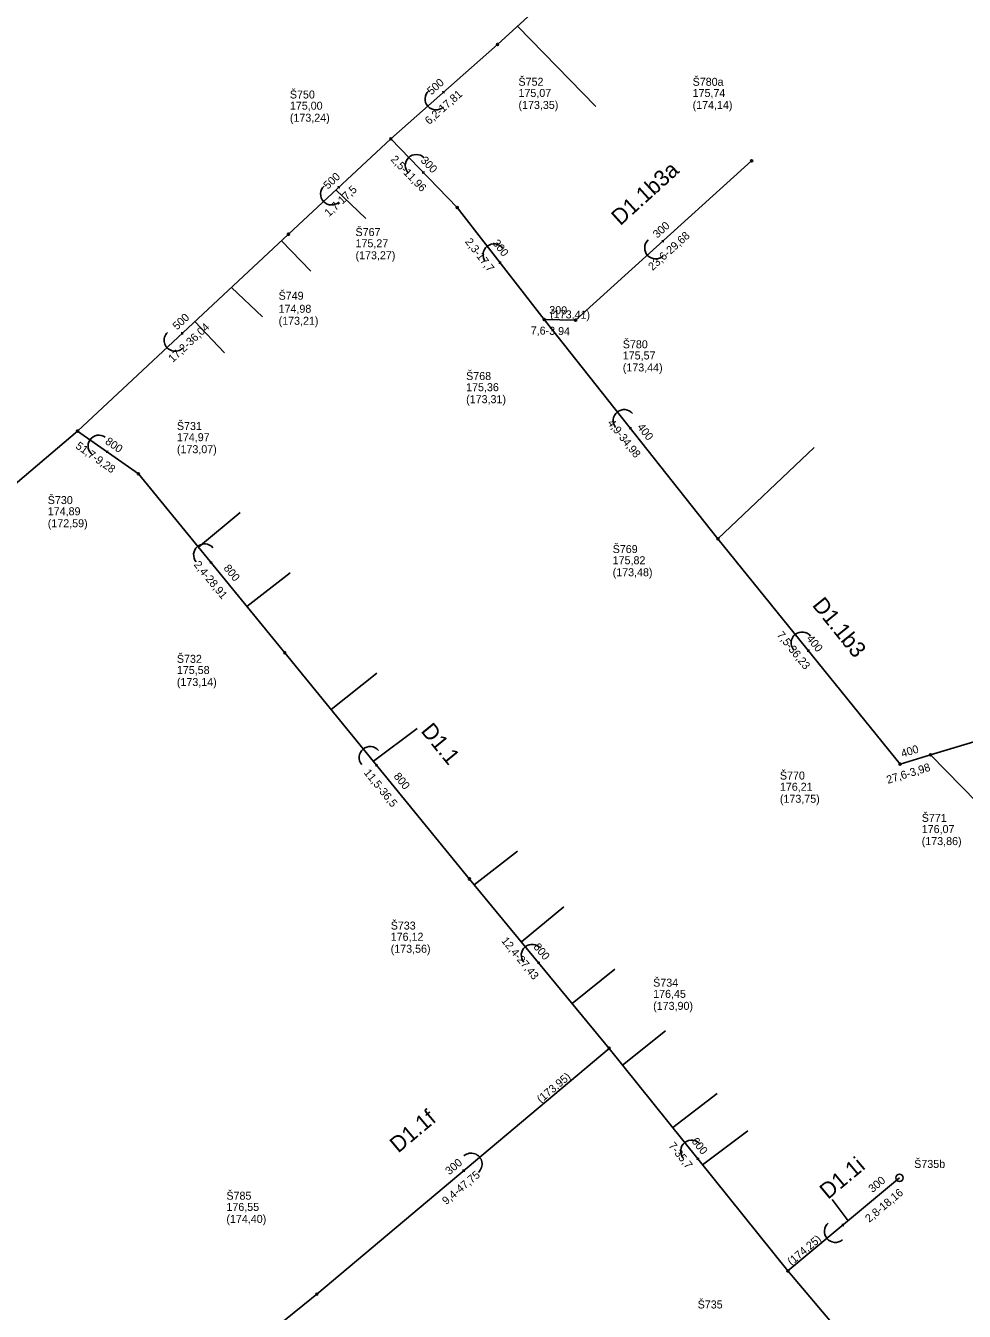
# Model space of a CAD drawing. Extents: x -548529 to -543591, y -1201432 to -1192608.
# Drawn here: x -544931.3 to -544814, y -1193635.3 to -1193474.6 of the extents above; entities that cross this region are included whole.
import ezdxf

# ---------------------------------------------------------------- set-up
doc = ezdxf.new("R2010")
doc.units = 0
for name, color, linetype in [('C3D_Bod-Značky', 7, 'Continuous'), ('C3D_Koridor', 7, 'Continuous'), ('C3D_Křižovatka', 7, 'Continuous'), ('C3D_Netisknutelná', 7, 'Continuous'), ('C3D_PP-zobrazeni v PR', 7, 'Continuous'), ('C3D_PR-Popisek', 7, 'Continuous'), ('C3D_SPR-Popisek', 7, 'Continuous'), ('C3D_Tlakove_potrubi_Popis', 7, 'Continuous'), ('C3D_ZPR-Formaty', 7, 'Continuous')]:
    doc.layers.add(name, color=color, linetype=linetype)

# ---------------------------------------------------------------- blocks, each defined once
blk = doc.blocks.new('100')
at = {"layer": 'Defpoints'}
blk.add_circle((0, 0), 0.127, dxfattribs=at)
blk = doc.blocks.new('101')
at = {"layer": 'Defpoints'}
blk.add_circle((0, 0), 0.463, dxfattribs=at)
blk = doc.blocks.new('91')
at = {"layer": 'Defpoints'}
blk.add_lwpolyline([(0.08, 0.14), (0.19, 0), (0.08, -0.14)], dxfattribs=at)
blk.add_arc((1.37, 0), 1.37, 270, 90, dxfattribs=at)
blk = doc.blocks.new('86')
at = {"layer": 'Defpoints'}
blk.add_lwpolyline([(0.08, 0.14), (0.19, 0), (0.08, -0.14)], dxfattribs=at)
blk.add_arc((1.37, 0), 1.37, 270, 90, dxfattribs=at)

msp = doc.modelspace()

# ---------------------------------------------------------------- linework, layer by layer
at = {"layer": 'C3D_Bod-Značky'}
for points in [[(-544851.303, -1193457.748), (-544872.308, -1193476.946)], [(-544872.308, -1193476.946), (-544885.651, -1193488.75)], [(-544885.651, -1193488.75), (-544898.453, -1193500.683)], [(-544877.337, -1193497.346), (-544885.651, -1193488.75)], [(-544840.54, -1193491.5), (-544862.54, -1193511.42)], [(-544866.481, -1193511.325), (-544877.337, -1193497.346)], [(-544898.453, -1193500.683), (-544924.795, -1193525.275)], [(-544844.754, -1193538.736), (-544866.481, -1193511.325)], [(-544862.54, -1193511.42), (-544866.481, -1193511.325)], [(-544924.795, -1193525.275), (-544947.898, -1193544.875)], [(-544917.202, -1193530.615), (-544924.795, -1193525.275)], [(-544898.887, -1193552.989), (-544917.202, -1193530.615)], [(-544821.99, -1193566.92), (-544844.754, -1193538.736)], [(-544875.81, -1193581.27), (-544898.887, -1193552.989)], [(-544802.07, -1193560.9), (-544818.19, -1193565.74)], [(-544818.19, -1193565.74), (-544821.99, -1193566.92)], [(-544858.362, -1193602.437), (-544875.81, -1193581.27)], [(-544894.906, -1193633.168), (-544858.362, -1193602.437)], [(-544836, -1193630.262), (-544858.362, -1193602.437)], [(-544822.063, -1193618.624), (-544836, -1193630.262)], [(-544821.397, -1193647.55), (-544836, -1193630.262)], [(-544920.416, -1193653.842), (-544894.906, -1193633.168)]]:
    msp.add_lwpolyline(points, dxfattribs=at)
at = {"layer": 'C3D_Koridor'}
for points in [[(-544869.808, -1193474.661), (-544860.021, -1193484.722)], [(-544892.504, -1193495.141), (-544888.751, -1193498.717)], [(-544899.33, -1193501.502), (-544895.655, -1193505.284)], [(-544905.565, -1193507.323), (-544901.693, -1193510.985)], [(-544910.127, -1193511.581), (-544906.416, -1193515.501)], [(-544844.754, -1193538.736), (-544832.714, -1193527.337)], [(-544909.703, -1193539.776), (-544904.495, -1193535.469)], [(-544903.631, -1193547.193), (-544898.246, -1193542.989)], [(-544893.108, -1193560.071), (-544887.4, -1193555.53)], [(-544887.83, -1193566.539), (-544882.339, -1193562.478)], [(-544818.19, -1193565.74), (-544794.95, -1193589.492)], [(-544875.219, -1193581.987), (-544869.818, -1193577.785)], [(-544869.324, -1193589.139), (-544864.037, -1193584.764)], [(-544862.978, -1193596.837), (-544857.632, -1193592.55)], [(-544856.677, -1193604.534), (-544851.308, -1193600.24)], [(-544850.407, -1193612.336), (-544844.848, -1193608.09)], [(-544846.669, -1193616.987), (-544841.008, -1193612.737)], [(-544828.495, -1193623.995), (-544830.467, -1193621.345)]]:
    msp.add_lwpolyline(points, dxfattribs=at)

# ---------------------------------------------------------------- block references
at = {"layer": 'C3D_PP-zobrazeni v PR'}
for name, p, xscale, yscale, rotation in [('100', (-544872.308, -1193476.946), 1.0000000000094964, 1.0000000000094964, -137.9999986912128), ('100', (-544885.651, -1193488.75), 1.00000000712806, 1.00000000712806, -136.99999943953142), ('100', (-544840.54, -1193491.5), 1.00000000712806, 1.00000000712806, 43.0000005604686), ('100', (-544877.337, -1193497.346), 1.0000000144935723, 1.0000000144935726, 130.99999910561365), ('100', (-544898.453, -1193500.683), 1.0000000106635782, 1.0000000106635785, -135.99999834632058), ('100', (-544866.481, -1193511.325), 1.000000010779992, 1.0000000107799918, 128.99999891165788), ('100', (-544862.54, -1193511.42), 1.0275072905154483, 1.027507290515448, -155.31089431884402), ('100', (-544924.795, -1193525.275), 1.0002788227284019, 1.0002788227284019, -176.70930040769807), ('100', (-544917.202, -1193530.615), 1.0000000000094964, 1.0000000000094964, 137.9999986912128), ('100', (-544844.754, -1193538.736), 1.000000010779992, 1.0000000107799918, 128.99999891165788), ('100', (-544898.887, -1193552.989), 1.0000000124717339, 1.0000000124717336, 130.0000013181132), ('100', (-544821.99, -1193566.92), 1.0365458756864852, 1.0365458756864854, 158.02850914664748), ('100', (-544818.19, -1193565.74), 1.035124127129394, 1.0351241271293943, -157.49634583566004), ('100', (-544875.81, -1193581.27), 1.0000000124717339, 1.0000000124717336, 130.0000013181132), ('100', (-544858.362, -1193602.437), 1.0000000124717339, 1.0000000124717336, 130.0000013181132), ('101', (-544822.063, -1193618.624), 1.0000000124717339, 1.0000000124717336, 40.00000131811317), ('100', (-544836, -1193630.262), 1.0000000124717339, 1.0000000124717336, 130.0000013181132), ('100', (-544894.906, -1193633.168), 1.0000000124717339, 1.0000000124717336, -139.99999868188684)]:
    msp.add_blockref(name, p, dxfattribs=dict(at, xscale=xscale, yscale=yscale, rotation=rotation))
at = {"layer": 'C3D_SPR-Popisek'}
for name, p, xscale, yscale, rotation in [('91', (-544878.979, -1193482.848), 1.0000000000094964, 1.0000000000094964, -137.9999986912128), ('91', (-544881.494, -1193493.048), 0.999999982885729, 0.9999999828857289, 135), ('91', (-544892.052, -1193494.716), 1.00000000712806, 1.00000000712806, -136.99999943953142), ('91', (-544851.54, -1193501.46), 1.00000000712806, 1.00000000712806, -136.99999943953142), ('91', (-544871.909, -1193504.336), 1.000000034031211, 1.0000000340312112, 128.00000040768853), ('91', (-544911.624, -1193512.979), 1.0000000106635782, 1.0000000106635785, -135.99999834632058), ('86', (-544855.617, -1193525.03), 1.000000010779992, 1.0000000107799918, 128.99999891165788), ('91', (-544920.998, -1193527.945), 1.000000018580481, 1.000000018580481, 144.99999976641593), ('91', (-544908.045, -1193541.802), 1.0000000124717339, 1.0000000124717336, 130.0000013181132), ('86', (-544833.372, -1193552.828), 1.000000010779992, 1.0000000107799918, 128.99999891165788), ('91', (-544887.349, -1193567.13), 1.0000000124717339, 1.0000000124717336, 130.0000013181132), ('91', (-544867.086, -1193591.854), 1.0000000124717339, 1.0000000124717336, 130.0000013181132), ('91', (-544847.181, -1193616.35), 1.000000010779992, 1.0000000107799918, 128.99999891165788), ('91', (-544876.634, -1193617.802), 1.0000000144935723, 1.0000000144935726, 40.99999910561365), ('91', (-544829.032, -1193624.443), 1.0000000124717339, 1.0000000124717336, -139.99999868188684)]:
    msp.add_blockref(name, p, dxfattribs=dict(at, xscale=xscale, yscale=yscale, rotation=rotation))

# ---------------------------------------------------------------- texts
at = {"layer": 'C3D_Křižovatka'}
for s, p in [('Š752', (-544869.688, -1193482.116)), ('Š780a', (-544847.92, -1193482.12)), ('Š750', (-544898.261, -1193483.71)), ('Š767', (-544890.057, -1193500.906)), ('Š749', (-544899.673, -1193508.863)), ('Š780', (-544856.65, -1193514.93)), ('Š768', (-544876.231, -1193518.895)), ('Š731', (-544912.382, -1193525.145)), ('Š730', (-544928.525, -1193534.405)), ('Š769', (-544857.914, -1193540.526)), ('Š732', (-544912.387, -1193554.249)), ('Š770', (-544837.01, -1193568.84)), ('Š771', (-544819.28, -1193574.13)), ('Š733', (-544885.66, -1193587.59)), ('Š734', (-544852.852, -1193594.727)), ('Š735b', (-544820.223, -1193617.384)), ('Š785', (-544906.196, -1193621.358)), ('Š735', (-544847.29, -1193634.952))]:
    msp.add_text(s, height=1, dxfattribs=at).set_placement(p)
at = {"layer": 'C3D_Netisknutelná'}
for s, rotation, p in [('D1.1b3a', 42.16, (-544856.962, -1193499.677)), ('D1.1b3', 308.93, (-544833.053, -1193547.071)), ('D1.1', 309.21, (-544881.976, -1193562.795)), ('D1.1f', 40.06, (-544884.72, -1193615.594)), ('D1.1i', 39.86, (-544830.998, -1193621.392))]:
    msp.add_text(s, height=2, rotation=rotation, dxfattribs=at).set_placement(p)
at = {"layer": 'C3D_PR-Popisek'}
for s, rotation, p in [('500', 41.5, (-544880.575, -1193483.331)), ('300', 314.04, (-544881.994, -1193491.522)), ('500', 42.99, (-544893.51, -1193495.115)), ('300', 42.16, (-544852.34, -1193501.236)), ('300', 307.83, (-544872.994, -1193501.8)), ('300', 358.62, (-544865.853, -1193510.64)), ('500', 43.03, (-544912.367, -1193512.712)), ('400', 308.4, (-544854.905, -1193524.806)), ('800', 324.88, (-544921.436, -1193526.779)), ('800', 309.3, (-544906.609, -1193542.444)), ('400', 308.93, (-544833.74, -1193551.261)), ('400', 17.25, (-544821.706, -1193566.095)), ('800', 309.21, (-544885.354, -1193568.459)), ('800', 309.5, (-544867.876, -1193589.787)), ('600', 308.79, (-544848.118, -1193614.069)), ('300', 40.06, (-544878.327, -1193618.316)), ('300', 39.86, (-544825.436, -1193620.533))]:
    msp.add_text(s, height=1, rotation=rotation, dxfattribs=at).set_placement(p)
at = {"layer": 'C3D_Tlakove_potrubi_Popis'}
for s, p in [('175,07 ', (-544869.688, -1193483.516)), ('175,74 ', (-544847.92, -1193483.52)), ('175,00 ', (-544898.261, -1193485.11)), ('(173,35)', (-544869.688, -1193485.016)), ('(174,14)', (-544847.92, -1193485.02)), ('(173,24)', (-544898.261, -1193486.61)), ('175,27 ', (-544890.057, -1193502.306)), ('(173,27)', (-544890.057, -1193503.806)), ('174,98 ', (-544899.673, -1193510.493)), ('(173,21)', (-544899.673, -1193511.993)), ('175,57 ', (-544856.65, -1193516.33)), ('(173,44)', (-544856.65, -1193517.83)), ('175,36 ', (-544876.231, -1193520.295)), ('(173,31)', (-544876.231, -1193521.795)), ('174,97 ', (-544912.382, -1193526.545)), ('(173,07)', (-544912.382, -1193528.045)), ('(172,59)', (-544928.525, -1193537.305)), ('174,89 ', (-544928.525, -1193535.805)), ('175,82 ', (-544857.914, -1193541.926)), ('(173,48)', (-544857.914, -1193543.426)), ('175,58 ', (-544912.387, -1193555.649)), ('(173,14)', (-544912.387, -1193557.149)), ('176,21 ', (-544837.01, -1193570.24)), ('(173,75)', (-544837.01, -1193571.74)), ('176,07 ', (-544819.28, -1193575.53)), ('(173,86)', (-544819.28, -1193577.03)), ('176,12 ', (-544885.66, -1193588.99)), ('(173,56)', (-544885.66, -1193590.49)), ('176,45 ', (-544852.852, -1193596.127)), ('(173,90)', (-544852.852, -1193597.627)), ('176,55 ', (-544906.196, -1193622.758)), ('(174,40)', (-544906.196, -1193624.258))]:
    msp.add_text(s, height=1, dxfattribs=at).set_placement(p)
at = {"layer": 'C3D_ZPR-Formaty'}
for s, rotation, p in [('6,2-17,81', 41.5, (-544880.849, -1193487.038)), ('2,5-11,96', 314.04, (-544885.737, -1193491.394)), ('1,7-17,5', 42.99, (-544893.381, -1193498.554)), ('23,6-29,68', 42.16, (-544852.925, -1193505.278)), ('2,3-17,7', 307.83, (-544876.42, -1193501.622)), ('  (173,41)   ', 358.62, (-544866.476, -1193511.125)), ('17,2-36,04', 43.03, (-544912.895, -1193516.765)), ('7,6-3,94', 358.62, (-544868.166, -1193513.185)), ('4,9-34,98', 308.4, (-544858.619, -1193524.299)), ('51,7-9,28', 324.88, (-544925.14, -1193527.351)), ('2,4-28,91', 309.3, (-544910.333, -1193542.001)), ('7,5-36,23', 308.93, (-544837.455, -1193550.79)), ('11,5-36,5', 309.21, (-544889.076, -1193568.012)), ('27,6-3,98', 17.25, (-544823.509, -1193569.383)), ('12,4-27,43', 309.5, (-544871.89, -1193589.017)), ('  (173,95)   ', 40.06, (-544867.446, -1193609.814)), ('7-35,7', 308.79, (-544850.995, -1193614.644)), ('9,4-47,75', 40.06, (-544878.722, -1193622.045)), ('2,8-18,16', 39.86, (-544825.842, -1193624.258)), ('  (174,25)   ', 39.86, (-544836.128, -1193630.108))]:
    msp.add_text(s, height=1, rotation=rotation, dxfattribs=at).set_placement(p)

doc.saveas('drawing.dxf')
